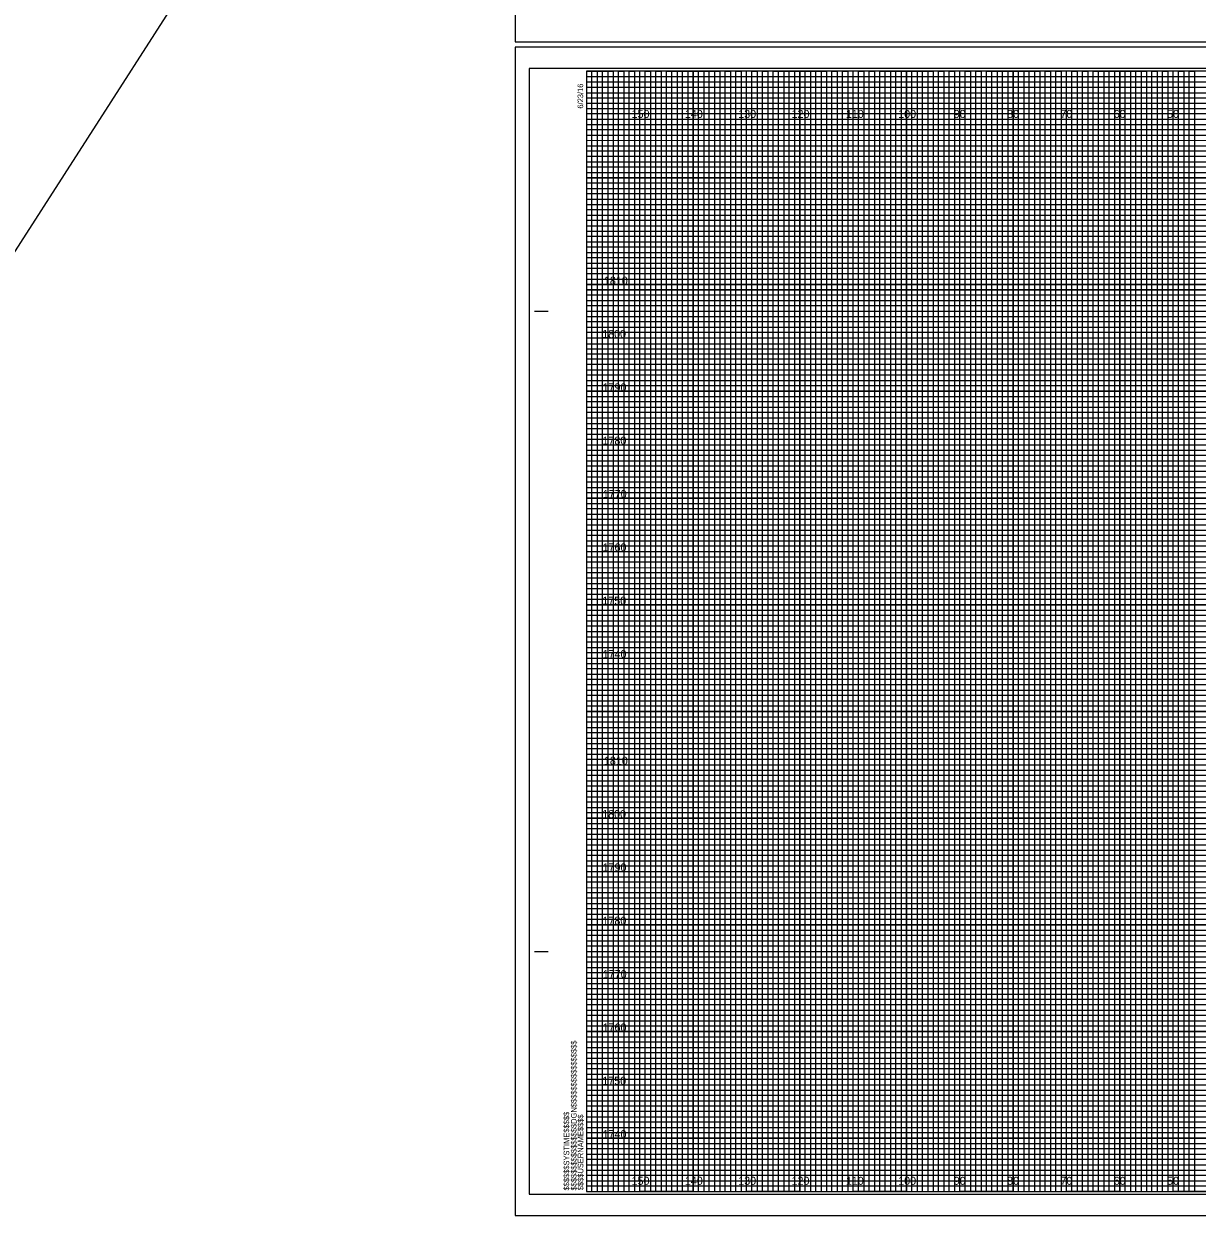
# Model space of a CAD drawing. Extents: x -419 to 4739, y -630 to 13534.
# Drawn here: x 384 to 604.1, y 647.5 to 871.4 of the extents above; entities that cross this region are included whole.
import ezdxf

# ---------------------------------------------------------------- set-up
doc = ezdxf.new("R2010")
doc.units = 0
for name, color, linetype in [('Old_Level_62', 7, 'Continuous'), ('Pattern 1', 7, 'Continuous'), ('Pattern 18', 7, 'Continuous'), ('Pattern 4', 7, 'Continuous'), ('Pattern 5', 7, 'Continuous'), ('Prop Dimension', 7, 'Continuous'), ('Prop Horizontal Alignment', 7, 'Continuous'), ('Raster_Level_0', 7, 'Continuous'), ('Scratch_Level_0', 7, 'Continuous'), ('Scratch_Level_3', 7, 'Continuous'), ('Scratch_Level_5', 7, 'Continuous')]:
    doc.layers.add(name, color=color, linetype=linetype)

msp = doc.modelspace()

# ---------------------------------------------------------------- linework, layer by layer
at = {"layer": 'Old_Level_62'}
for p, q in [((479.78, 817.54), (482.28, 817.54)), ((479.88, 817.54), (482.38, 817.54)), ((479.78, 697.54), (482.28, 697.54)), ((479.88, 697.54), (482.38, 697.54)), ((489.58, 652.54), (489.58, 652.54)), ((489.58, 652.54), (489.58, 652.54)), ((489.58, 652.54), (489.58, 652.54)), ((489.58, 652.54), (489.58, 652.54)), ((489.58, 652.54), (489.58, 652.54)), ((489.58, 652.54), (489.58, 652.54)), ((489.58, 652.54), (489.58, 652.54))]:
    msp.add_line(p, q, dxfattribs=at)
msp.add_lwpolyline([(809.58, 862.54), (489.58, 862.54), (489.58, 652.54), (809.58, 652.54)], close=True, dxfattribs=at)
at = {"layer": 'Pattern 18'}
msp.add_line((-419.01, -416.83), (1573.75, 2680.65), dxfattribs=at)
for points in [[(476.18, 868.04), (812.88, 868.04), (812.88, 1087.04), (476.18, 1087.04)], [(476.18, 648.04), (812.88, 648.04), (812.88, 867.04), (476.18, 867.04)]]:
    msp.add_lwpolyline(points, close=True, dxfattribs=at)
at = {"layer": 'Pattern 4'}
for p, q in [((489.58, 861.54), (749.58, 861.54)), ((749.58, 860.52), (489.58, 860.52)), ((489.58, 860.52), (489.58, 859.54)), ((489.58, 859.54), (749.58, 859.54)), ((749.58, 858.43), (489.58, 858.43)), ((489.58, 858.43), (489.58, 856.54)), ((489.58, 856.54), (809.58, 856.54))]:
    msp.add_line(p, q, dxfattribs=at)
for points in [[(489.58, 855.54), (759.58, 855.54), (809.58, 855.54), (809.58, 854.54), (489.58, 854.54)], [(489.58, 853.54), (809.58, 853.54), (809.58, 851.54), (489.58, 851.54)], [(489.58, 850.54), (809.58, 850.54), (809.58, 849.54), (489.58, 849.52)], [(489.58, 848.54), (809.58, 848.54), (809.58, 846.54), (489.58, 846.54)], [(489.58, 845.54), (809.58, 845.54), (809.58, 844.54), (489.58, 844.54)], [(489.58, 843.54), (809.58, 843.54), (809.58, 841.54), (489.58, 841.54)], [(489.58, 840.54), (809.58, 840.54), (809.58, 839.54), (489.58, 839.54)], [(489.58, 838.54), (809.58, 838.54), (809.58, 836.54), (489.58, 836.54)], [(489.58, 835.54), (809.58, 835.54), (809.58, 834.54), (489.58, 834.54)], [(489.58, 833.54), (809.58, 833.54), (809.58, 831.54), (489.58, 831.54)], [(489.58, 830.54), (809.58, 830.54), (809.58, 829.54), (489.58, 829.54)], [(489.58, 828.54), (809.58, 828.54), (809.58, 826.49), (809.58, 825.54), (809.58, 824.54), (489.58, 824.54)], [(489.58, 826.54), (809.58, 826.54), (809.58, 825.54), (489.58, 825.54)], [(489.58, 823.54), (809.58, 823.54), (809.58, 821.54), (489.58, 821.57)], [(489.58, 821.57), (809.58, 821.54), (809.58, 820.54), (489.58, 820.54)], [(489.58, 819.54), (809.58, 819.54), (809.58, 818.54), (489.58, 818.54)], [(489.58, 816.54), (809.58, 816.54), (809.58, 815.54), (489.58, 815.54)], [(489.58, 814.54), (809.58, 814.54), (809.58, 813.54), (489.58, 813.54)], [(489.51, 811.43), (809.58, 811.43), (809.58, 810.42), (489.51, 810.42)], [(489.58, 809.54), (809.58, 809.54), (809.58, 808.54), (489.58, 808.54)], [(489.58, 806.54), (809.58, 806.54), (809.58, 805.54), (489.58, 805.54)], [(489.58, 804.54), (809.58, 804.54), (809.58, 803.54), (489.58, 803.54)], [(489.58, 801.54), (809.58, 801.54), (809.58, 800.54), (489.58, 800.54)], [(489.58, 799.54), (809.58, 799.54), (809.58, 798.54), (489.58, 798.54)], [(489.58, 796.54), (809.58, 796.54), (809.58, 795.54), (489.58, 795.54)], [(489.58, 794.54), (809.58, 794.54), (809.58, 793.54), (489.58, 793.54)], [(489.58, 791.54), (809.58, 791.54), (809.57, 790.52), (489.58, 790.54)], [(489.58, 789.54), (809.58, 789.54), (809.58, 788.54), (489.58, 788.54)], [(489.58, 786.54), (809.58, 786.54), (809.58, 785.54), (489.58, 785.54)], [(489.58, 784.54), (809.58, 784.54), (809.58, 783.54), (489.58, 783.54)], [(489.58, 781.54), (809.58, 781.54), (809.58, 780.54), (489.58, 780.54)], [(489.58, 779.54), (809.58, 779.54), (809.58, 778.54), (489.58, 778.54)], [(489.58, 776.54), (809.58, 776.54), (809.58, 775.54), (489.58, 775.54)], [(489.58, 774.54), (809.58, 774.54), (809.58, 773.54), (489.58, 773.54)], [(489.58, 771.54), (809.58, 771.54), (809.58, 770.54), (489.58, 770.54)], [(489.58, 769.53), (809.65, 769.45), (809.58, 768.54), (489.58, 768.54)], [(489.58, 766.54), (809.58, 766.54), (809.58, 765.54), (489.58, 765.54)], [(489.58, 764.54), (809.58, 764.54), (809.58, 763.54), (489.58, 763.54)], [(489.58, 761.54), (809.58, 761.54), (809.58, 760.54), (489.58, 760.54)], [(489.58, 759.54), (809.58, 759.54), (809.58, 758.54), (489.58, 758.54)], [(489.58, 756.54), (809.58, 756.54), (809.58, 755.54), (489.58, 755.54)], [(489.58, 754.54), (809.58, 754.54), (809.58, 753.54), (489.58, 753.54)], [(489.58, 751.54), (809.58, 751.54), (809.58, 750.54), (489.58, 750.54)], [(489.58, 749.54), (809.58, 749.54), (809.58, 748.54), (489.58, 748.54)], [(489.58, 746.54), (809.58, 746.54), (809.58, 745.54), (489.58, 745.54)], [(489.58, 744.54), (809.58, 744.54), (809.58, 743.54), (489.58, 743.54)], [(489.58, 741.54), (809.58, 741.54), (809.58, 740.54), (489.58, 740.54)], [(489.58, 739.54), (809.58, 739.54), (809.58, 738.54), (489.58, 738.54)], [(489.58, 736.54), (809.58, 736.54), (809.58, 735.54), (489.58, 735.54)], [(489.58, 734.54), (809.58, 734.54), (809.58, 733.54), (489.58, 733.54)], [(489.58, 731.54), (809.58, 731.54), (809.57, 730.52), (489.58, 730.54)], [(489.58, 729.54), (809.58, 729.54), (809.58, 728.54), (489.58, 728.54)], [(489.58, 726.54), (809.58, 726.54), (809.58, 725.54), (489.58, 725.54)], [(489.58, 724.54), (809.58, 724.54), (809.58, 723.54), (489.58, 723.54)], [(489.58, 721.54), (809.58, 721.54), (809.58, 720.54), (489.58, 720.54)], [(489.58, 719.54), (809.58, 719.54), (809.58, 718.54), (489.58, 718.54)], [(489.58, 716.54), (809.58, 716.54), (809.58, 715.54), (489.58, 715.54)], [(489.58, 714.54), (809.58, 714.54), (809.58, 713.54), (489.58, 713.54)], [(489.58, 711.54), (809.58, 711.54), (809.58, 710.54), (489.58, 710.54)], [(489.58, 709.53), (809.65, 709.45), (809.58, 708.54), (489.58, 708.54)], [(489.58, 706.54), (809.58, 706.54), (809.58, 705.54), (489.58, 705.54)], [(489.58, 704.54), (809.58, 704.54), (809.58, 703.54), (489.58, 703.54)], [(489.58, 701.54), (809.58, 701.54), (809.58, 700.54), (489.58, 700.54)], [(489.58, 699.54), (809.58, 699.54), (809.58, 698.54), (489.58, 698.54)], [(489.58, 696.54), (809.58, 696.54), (809.58, 695.54), (489.58, 695.54)], [(489.58, 694.54), (809.58, 694.54), (809.58, 693.54), (489.58, 693.54)], [(489.58, 691.54), (809.58, 691.54), (809.58, 690.54), (489.58, 690.54)], [(489.58, 689.54), (809.58, 689.54), (809.58, 688.54), (489.58, 688.54)], [(489.58, 686.54), (809.58, 686.54), (809.58, 685.54), (489.58, 685.54)], [(489.58, 684.54), (809.58, 684.54), (809.58, 683.54), (489.58, 683.54)], [(489.58, 681.54), (809.58, 681.54), (809.58, 680.54), (489.58, 680.54)], [(489.58, 679.54), (809.58, 679.54), (809.58, 678.54), (489.58, 678.54)], [(489.58, 676.54), (809.58, 676.54), (809.58, 675.54), (489.58, 675.54)], [(489.58, 674.54), (809.58, 674.54), (809.58, 673.54), (489.58, 673.54)], [(489.58, 671.54), (809.58, 671.54), (809.58, 670.54), (489.58, 670.54)], [(489.58, 669.54), (809.58, 669.54), (809.58, 668.54), (489.58, 668.54)], [(489.58, 666.54), (809.58, 666.54), (809.58, 665.54), (489.58, 665.54)], [(489.58, 664.54), (809.58, 664.54), (809.58, 663.54), (489.58, 663.54)], [(489.58, 661.54), (809.58, 661.54), (809.58, 660.54), (489.58, 660.54)], [(489.58, 659.54), (809.58, 659.54), (809.58, 658.54), (489.58, 658.54)], [(489.58, 656.54), (809.58, 656.54), (809.58, 655.54), (489.58, 655.54)], [(489.58, 654.54), (809.58, 654.54), (809.58, 653.54), (489.58, 653.54)]]:
    msp.add_lwpolyline(points, dxfattribs=at)
at = {"layer": 'Pattern 5'}
for p, q in [((476.18, 1087.04), (476.18, 868.04)), ((476.18, 868.04), (812.88, 868.04)), ((812.88, 867.04), (476.18, 867.04)), ((476.18, 867.04), (476.18, 648.04)), ((476.18, 648.04), (812.88, 648.04))]:
    msp.add_line(p, q, dxfattribs=at)
at = {"layer": 'Prop Dimension'}
for points in [[(489.58, 652.54), (490.58, 652.54), (490.58, 862.54), (491.58, 862.54), (491.58, 652.54)], [(491.58, 652.54), (492.58, 652.54), (492.58, 862.54), (493.58, 862.54), (493.58, 652.54)], [(494.58, 652.54), (495.58, 652.54), (495.58, 862.54), (496.58, 862.54), (496.58, 652.54)], [(496.58, 652.54), (497.58, 652.54), (497.58, 862.54), (498.58, 862.54), (498.58, 652.54)], [(499.58, 652.54), (500.58, 652.54), (500.58, 862.54), (501.58, 862.54), (501.58, 652.54)], [(501.58, 652.54), (502.58, 652.54), (502.58, 862.54), (503.58, 862.54), (503.58, 652.54)], [(504.58, 652.54), (505.58, 652.54), (505.58, 862.54), (506.58, 862.54), (506.58, 652.54)], [(506.58, 652.54), (507.58, 652.54), (507.58, 862.54), (508.58, 862.54), (508.58, 652.54)], [(509.58, 652.54), (510.58, 652.54), (510.58, 862.54), (511.58, 862.54), (511.58, 652.54)], [(511.58, 652.54), (512.58, 652.54), (512.58, 862.54), (513.58, 862.54), (513.58, 652.54)], [(514.58, 652.54), (515.58, 652.54), (515.58, 862.54), (516.58, 862.54), (516.58, 652.54)], [(516.58, 652.54), (517.58, 652.54), (517.58, 862.54), (518.58, 862.54), (518.58, 652.54)], [(519.58, 652.54), (520.58, 652.54), (520.58, 862.54), (521.58, 862.54), (521.58, 652.54)], [(521.58, 652.54), (522.58, 652.54), (522.58, 862.54), (523.58, 862.54), (523.58, 652.54)], [(524.58, 652.54), (525.58, 652.54), (525.58, 862.54), (526.58, 862.54), (526.58, 652.54)], [(526.58, 652.54), (527.58, 652.54), (527.58, 862.54), (528.58, 862.54), (528.58, 652.54)], [(529.58, 652.54), (530.58, 652.54), (530.58, 862.54), (531.58, 862.54), (531.58, 652.54)], [(531.58, 652.54), (532.58, 652.54), (532.58, 862.54), (533.58, 862.54), (533.58, 652.54)], [(534.58, 652.54), (535.58, 652.54), (535.58, 862.54), (536.58, 862.54), (536.58, 652.54)], [(536.58, 652.54), (537.58, 652.54), (537.58, 862.54), (538.58, 862.54), (538.58, 652.54)], [(539.58, 652.54), (540.58, 652.54), (540.58, 862.54), (541.58, 862.54), (541.58, 652.54)], [(541.58, 652.54), (542.58, 652.54), (542.58, 862.54), (543.58, 862.54), (543.58, 652.54)], [(544.58, 652.54), (545.58, 652.54), (545.58, 862.54), (546.58, 862.54), (546.58, 652.54)], [(546.58, 652.54), (547.58, 652.54), (547.58, 862.54), (548.58, 862.54), (548.58, 652.54)], [(549.58, 652.54), (550.58, 652.54), (550.58, 862.54), (551.58, 862.54), (551.58, 652.54)], [(551.58, 652.54), (552.58, 652.54), (552.58, 862.54), (553.58, 862.54), (553.58, 652.54)], [(554.58, 652.54), (555.58, 652.54), (555.58, 862.54), (556.58, 862.54), (556.58, 652.54)], [(556.58, 652.54), (557.58, 652.54), (557.58, 862.54), (558.58, 862.54), (558.58, 652.54)], [(559.58, 652.54), (560.58, 652.54), (560.58, 862.54), (561.58, 862.54), (561.58, 652.54)], [(561.58, 652.54), (562.58, 652.54), (562.58, 862.54), (563.58, 862.54), (563.58, 652.54)], [(564.58, 652.54), (565.58, 652.54), (565.58, 862.54), (566.58, 862.54), (566.58, 652.54)], [(566.58, 652.54), (567.58, 652.54), (567.58, 862.54), (568.58, 862.54), (568.58, 652.54)], [(569.58, 652.54), (570.58, 652.54), (570.58, 862.54), (571.58, 862.54), (571.58, 652.54)], [(571.58, 652.54), (572.58, 652.54), (572.58, 862.54), (573.58, 862.54), (573.58, 652.54)], [(574.58, 652.54), (575.58, 652.54), (575.58, 862.54), (576.58, 862.54), (576.58, 652.54)], [(576.58, 652.54), (577.58, 652.54), (577.58, 862.54), (578.58, 862.54), (578.58, 652.54)], [(579.58, 652.54), (580.58, 652.54), (580.58, 862.54), (581.58, 862.54), (581.58, 652.54)], [(581.58, 652.54), (582.58, 652.54), (582.58, 862.54), (583.58, 862.54), (583.58, 652.54)], [(584.58, 652.54), (585.58, 652.54), (585.58, 862.54), (586.58, 862.54), (586.58, 652.54)], [(586.58, 652.54), (587.58, 652.54), (587.58, 862.54), (588.58, 862.54), (588.58, 652.54)], [(589.58, 652.54), (590.58, 652.54), (590.58, 862.54), (591.58, 862.54), (591.58, 652.54)], [(591.58, 652.54), (592.58, 652.54), (592.58, 862.54), (593.58, 862.54), (593.58, 652.54)], [(594.58, 652.54), (595.58, 652.54), (595.58, 862.54), (596.58, 862.54), (596.58, 652.54)], [(596.58, 652.54), (597.58, 652.54), (597.58, 862.54), (598.58, 862.54), (598.58, 652.54)], [(599.58, 652.54), (600.58, 652.54), (600.58, 862.54), (601.58, 862.54), (601.58, 652.54)], [(601.58, 652.54), (602.58, 652.54), (602.58, 862.54), (603.58, 862.54), (603.58, 652.54)]]:
    msp.add_lwpolyline(points, dxfattribs=at)
at = {"layer": 'Prop Horizontal Alignment'}
for points in [[(489.58, 862.54), (494.58, 862.54), (494.58, 652.54), (504.58, 652.54), (504.58, 862.54), (514.58, 862.54), (514.58, 652.54), (524.58, 652.54), (524.58, 862.54), (534.58, 862.54), (534.58, 652.54), (544.58, 652.54), (544.58, 862.54), (554.58, 862.54), (554.58, 652.54), (564.58, 652.54), (564.58, 862.54), (574.58, 862.54), (574.58, 652.54), (584.58, 652.54), (584.58, 862.54), (594.58, 862.54), (594.58, 652.54), (604.58, 652.54)], [(489.58, 857.54), (764.58, 857.54)], [(489.58, 837.54), (809.58, 837.54), (809.58, 847.54), (489.58, 847.54)], [(489.58, 817.54), (809.58, 817.54), (809.58, 827.54), (489.58, 827.54)], [(489.58, 797.54), (809.58, 797.54), (809.58, 807.54), (489.58, 807.54)], [(489.58, 777.54), (809.58, 777.54), (809.58, 787.54), (489.58, 787.54)], [(489.58, 757.54), (809.58, 757.54), (809.58, 767.54), (489.58, 767.54)], [(489.58, 737.54), (809.58, 737.54), (809.58, 747.54), (489.58, 747.54)], [(489.58, 717.54), (809.58, 717.54), (809.58, 727.54), (489.58, 727.54)], [(489.58, 697.54), (809.58, 697.54), (809.58, 707.54), (489.58, 707.54)], [(489.58, 677.54), (809.58, 677.54), (809.58, 687.54), (489.58, 687.54)], [(489.58, 657.54), (809.58, 657.54), (809.58, 667.54), (489.58, 667.54)]]:
    msp.add_lwpolyline(points, dxfattribs=at)
at = {"layer": 'Scratch_Level_0'}
for p, q in [((499.58, 652.54), (499.58, 862.54)), ((509.58, 652.54), (509.58, 862.54)), ((519.58, 652.54), (519.58, 862.54)), ((529.58, 652.54), (529.58, 862.54)), ((539.58, 652.54), (539.58, 862.54)), ((549.58, 652.54), (549.58, 862.54)), ((559.58, 652.54), (559.58, 862.54)), ((569.58, 652.54), (569.58, 862.54)), ((579.58, 652.54), (579.58, 862.54)), ((589.58, 652.54), (589.58, 862.54)), ((599.58, 652.54), (599.58, 862.54)), ((489.58, 852.54), (809.58, 852.54)), ((489.58, 842.54), (809.58, 842.54)), ((489.58, 832.54), (809.58, 832.54)), ((489.58, 822.54), (809.58, 822.54)), ((489.58, 812.54), (809.58, 812.54)), ((489.58, 802.54), (809.58, 802.54)), ((489.58, 792.54), (809.58, 792.54)), ((489.58, 782.54), (809.58, 782.54)), ((489.58, 772.54), (809.58, 772.54)), ((489.58, 762.54), (809.58, 762.54)), ((489.58, 752.54), (809.58, 752.54)), ((489.58, 742.54), (809.58, 742.54)), ((489.58, 732.54), (809.58, 732.54)), ((489.58, 722.54), (809.58, 722.54)), ((489.58, 712.54), (809.58, 712.54)), ((489.58, 702.54), (809.58, 702.54)), ((489.58, 692.54), (809.58, 692.54)), ((489.58, 682.54), (809.58, 682.54)), ((489.58, 672.54), (809.58, 672.54)), ((489.58, 662.54), (809.58, 662.54))]:
    msp.add_line(p, q, dxfattribs=at)
at = {"layer": 'Scratch_Level_3'}
for p, q in [((499.58, 862.54), (489.58, 862.54)), ((499.58, 652.54), (499.58, 862.54)), ((519.58, 862.54), (509.58, 862.54)), ((509.58, 862.54), (509.58, 652.54)), ((519.58, 652.54), (519.58, 862.54)), ((539.58, 862.54), (529.58, 862.54)), ((529.58, 862.54), (529.58, 652.54)), ((539.58, 652.54), (539.58, 862.54)), ((559.58, 862.54), (549.58, 862.54)), ((549.58, 862.54), (549.58, 652.54)), ((559.58, 652.54), (559.58, 862.54)), ((579.58, 862.54), (569.58, 862.54)), ((569.58, 862.54), (569.58, 652.54)), ((579.58, 652.54), (579.58, 862.54)), ((599.58, 862.54), (589.58, 862.54)), ((589.58, 862.54), (589.58, 652.54)), ((599.58, 652.54), (599.58, 862.54)), ((509.58, 652.54), (499.58, 652.54)), ((529.58, 652.54), (519.58, 652.54)), ((549.58, 652.54), (539.58, 652.54)), ((569.58, 652.54), (559.58, 652.54)), ((589.58, 652.54), (579.58, 652.54)), ((609.58, 652.54), (599.58, 652.54))]:
    msp.add_line(p, q, dxfattribs=at)
for points in [[(489.58, 852.54), (809.58, 852.54), (809.58, 842.54), (489.58, 842.54)], [(489.58, 832.54), (809.58, 832.54), (809.58, 822.54), (489.58, 822.54)], [(489.58, 812.54), (809.58, 812.54), (809.58, 802.54), (489.58, 802.54)], [(489.58, 792.54), (809.58, 792.54), (809.58, 782.54), (489.58, 782.54)], [(489.58, 772.54), (809.58, 772.54), (809.58, 762.54), (489.58, 762.54)], [(489.58, 752.54), (809.58, 752.54), (809.58, 742.54), (489.58, 742.54)], [(489.58, 732.54), (809.58, 732.54), (809.58, 722.54), (489.58, 722.54)], [(489.58, 712.54), (809.58, 712.54), (809.58, 702.54), (489.58, 702.54)], [(489.58, 692.54), (809.58, 692.54), (809.58, 682.54), (489.58, 682.54)], [(489.58, 672.54), (809.58, 672.54), (809.58, 662.54), (489.58, 662.54)]]:
    msp.add_lwpolyline(points, dxfattribs=at)
at = {"layer": 'Scratch_Level_5'}
msp.add_lwpolyline([(478.78, 652.04), (811.98, 652.04), (811.98, 863.04), (478.78, 863.04)], close=True, dxfattribs=at)

# ---------------------------------------------------------------- texts
at = {"layer": 'Old_Level_62'}
for s, p in [('6/23/16', (488.93, 855.54)), ('$$$$$$$$$$$$$$$$DGN$$$$$$$$$$$$$$$$', (487.7, 652.72)), ('$$$$$$SYSTIME$$$$$', (486.32, 652.72)), ('$$$$USERNAME$$$$', (488.96, 652.77))]:
    msp.add_text(s, height=1.05, rotation=90, dxfattribs=at).set_placement(p)
at = {"layer": 'Pattern 1'}
for s, p in [('1810', (492.83, 822.54)), ('1800', (492.5, 812.54)), ('1790', (492.58, 802.54)), ('1780', (492.56, 792.54)), ('1770', (492.62, 782.54)), ('1760', (492.58, 772.54)), ('1750', (492.53, 762.54)), ('1740', (492.58, 752.54)), ('1810', (492.83, 732.54)), ('1800', (492.5, 722.54)), ('1790', (492.58, 712.54)), ('1780', (492.56, 702.54)), ('1770', (492.62, 692.54)), ('1760', (492.58, 682.54)), ('1750', (492.53, 672.54)), ('1740', (492.58, 662.54))]:
    msp.add_text(s, height=1.5, dxfattribs=at).set_placement(p)
at = {"layer": 'Raster_Level_0'}
for s, p in [('150', (498.02, 853.79)), ('140', (508.02, 853.79)), ('130', (518.02, 853.79)), ('120', (528.02, 853.79)), ('110', (538.2, 853.79)), ('100', (548.02, 853.79)), ('90', (558.44, 853.79)), ('80', (568.44, 853.79)), ('70', (578.44, 853.79)), ('60', (588.44, 853.79)), ('50', (598.44, 853.79)), ('150', (498.02, 653.79)), ('140', (508.02, 653.79)), ('130', (518.02, 653.79)), ('120', (528.02, 653.79)), ('110', (538.2, 653.79)), ('100', (548.02, 653.79)), ('90', (558.44, 653.79)), ('80', (568.44, 653.79)), ('70', (578.44, 653.79)), ('60', (588.44, 653.79)), ('50', (598.44, 653.79))]:
    msp.add_text(s, height=1.5, dxfattribs=at).set_placement(p)

doc.saveas('drawing.dxf')
